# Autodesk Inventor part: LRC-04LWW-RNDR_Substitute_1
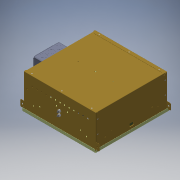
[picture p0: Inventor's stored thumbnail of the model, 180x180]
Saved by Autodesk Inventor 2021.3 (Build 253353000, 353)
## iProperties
Part Number: LRC-04LWW-RNDR_Substitute_1
Material: Generic
Document SubType Name: Modeling
Designer: JChurch
Manufacturer: Standard
Standards Organization: Custom
Density: 1 g/cm^3
Appearance: Smooth - Black
Author: JChurch
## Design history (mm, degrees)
derived "LRC-04LWW-RNDR.iam"
body "Solid9"
node "830520-00-00.ipt:1"
node "881088-00-00.iam:1::830140-00-00.ipt:1"
body "Solid10"
node "881088-00-00.iam:1::850014-00-00.iam:1::805044-00-00.ipt:1"
body "Solid11"
node "881088-00-00.iam:1::850014-00-00.iam:1::805174-00-00.ipt:1"
body "Solid12"
node "881088-00-00.iam:1::850014-00-00.iam:1::502055-00-00.ipt:1"
body "Solid13"
node "881088-00-00.iam:1::850014-00-00.iam:1::502055-00-00.ipt:2"
body "Solid14"
node "881088-00-00.iam:1::850014-00-00.iam:1::507032-00-00.ipt:1"
body "Solid15"
node "881088-00-00.iam:1::507000-00-00.ipt:1"
body "Solid16"
node "881088-00-00.iam:1::507000-00-00.ipt:2"
body "Solid17"
node "881088-00-00.iam:1::506002-00-00.ipt:1"
body "Solid18"
node "881088-00-00.iam:1::506002-00-00.ipt:2"
body "Solid19"
node "881088-00-00.iam:1::506002-00-00.ipt:3"
body "Solid20"
node "881088-00-00.iam:1::506002-00-00.ipt:4"
body "Solid21"
node "881088-00-00.iam:1::506002-00-00.ipt:5"
body "Solid22"
node "881088-00-00.iam:1::506002-00-00.ipt:6"
body "Solid23"
node "881088-00-00.iam:1::506002-00-00.ipt:7"
body "Solid24"
node "881088-00-00.iam:1::506002-00-00.ipt:8"
body "Solid25"
node "881088-00-00.iam:1::506002-00-00.ipt:9"
body "Solid26"
node "881088-00-00.iam:1::506002-00-00.ipt:10"
body "Solid27"
node "881088-00-00.iam:1::506002-00-00.ipt:11"
body "Solid28"
node "881088-00-00.iam:1::506002-00-00.ipt:12"
body "Solid29"
node "881088-00-00.iam:1::506002-00-00.ipt:13"
body "Solid30"
node "881088-00-00.iam:1::506002-00-00.ipt:14"
body "Solid31"
node "881088-00-00.iam:1::830392-01-00.iam:1::830392-00-00.ipt:1"
body "Solid32"
node "881088-00-00.iam:1::830392-01-00.iam:1::500027-00-00.ipt:1"
body "Solid33"
node "881088-00-00.iam:1::830392-01-00.iam:1::501030-00-00.ipt:1"
body "Solid34"
node "881088-00-00.iam:1::830392-01-00.iam:1::500027-00-00.ipt:2"
body "Solid35"
node "881088-00-00.iam:1::830392-01-00.iam:1::501030-00-00.ipt:2"
body "Solid36"
node "881088-00-00.iam:1::830392-01-00.iam:1::501030-00-00.ipt:3"
body "Solid37"
node "881088-00-00.iam:1::830392-01-00.iam:1::501030-00-00.ipt:4"
body "Solid38"
node "881088-00-00.iam:1::830392-01-00.iam:2::830392-00-00.ipt:1"
body "Solid39"
node "881088-00-00.iam:1::830392-01-00.iam:2::500027-00-00.ipt:1"
body "Solid40"
node "881088-00-00.iam:1::830392-01-00.iam:2::501030-00-00.ipt:1"
body "Solid41"
node "881088-00-00.iam:1::830392-01-00.iam:2::500027-00-00.ipt:2"
body "Solid42"
node "881088-00-00.iam:1::830392-01-00.iam:2::501030-00-00.ipt:2"
body "Solid43"
node "881088-00-00.iam:1::830392-01-00.iam:2::501030-00-00.ipt:3"
body "Solid44"
node "881088-00-00.iam:1::830392-01-00.iam:2::501030-00-00.ipt:4"
body "Solid45"
node "750460-00-XX.iam:1::750450-00-XX.iam:1::700483-20-XX.ipt:1"
body "Solid46"
node "750460-00-XX.iam:1::750450-00-XX.iam:1::710155-00-00.ipt:1"
body "Solid47"
node "750460-00-XX.iam:1::507035-01-38.ipt:1"
body "Solid48"
node "750460-00-XX.iam:1::507035-01-38.ipt:2"
body "Solid49"
node "750460-00-XX.iam:1::510051-00-00.ipt:1"
body "Solid50"
node "725377-01-00.ipt:1"
body "Solid51"
other parameters: "d15" = 61.595, "d16" = 9.525, "d17" = 9.525, "d35" = 5.08
